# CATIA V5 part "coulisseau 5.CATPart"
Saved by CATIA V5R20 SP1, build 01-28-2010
Part number: coulisseau 5
Bounding box of the stored display mesh (mm): x 360 to 380, y -27.5 to -12.5, z 0 to 15
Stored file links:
  E:\EDELI\wjacquemont\Edeli_2012_122_wjacquemont\coulisseau 5.CATPart
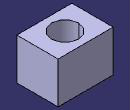
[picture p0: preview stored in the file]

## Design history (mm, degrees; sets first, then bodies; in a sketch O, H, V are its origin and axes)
Body1 (main body)
  Sketch1 on xy-plane, origin (0, 0, 0), H (1, 0, 0), V (0, 1, 0)
    line L1 (360, -12.5) -> (380, -12.5)
    line L2 (380, -12.5) -> (380, -27.5)
    line L3 (380, -27.5) -> (360, -27.5)
    line L4 (360, -27.5) -> (360, -12.5)
    circle A1 centre (370, -20) radius 5
    point P5 (370, -20)
    length L3 = 20
    distance L3 L1 = 15
    radius A1 = 5
    horizontal: L1 H, L3 H
    vertical: L2 V, L4 V
    equidistance: L1 L3 P5, L4 L2 P5
  Pad1: profile Sketch1, direction (0, 0, 1), length 15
